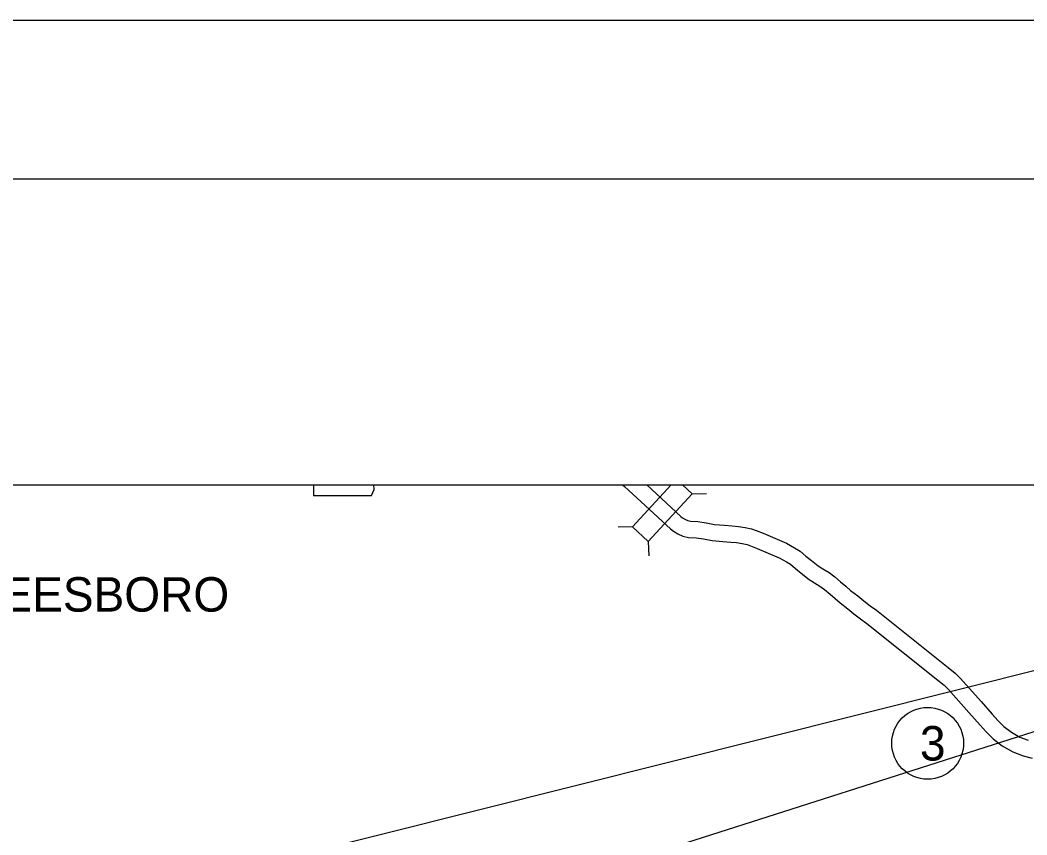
# Model space of a CAD drawing. Extents: x 79818 to 83933, y 50884 to 53307.
# Drawn here: x 81014.4 to 81261.3, y 53107.7 to 53307.5 of the extents above; entities that cross this region are included whole.
import ezdxf

# ---------------------------------------------------------------- set-up
doc = ezdxf.new("R2010")
doc.units = 0
for name, color, linetype in [('Default', 7, 'Continuous'), ('Level 10', 7, 'Continuous'), ('Level 20', 7, 'Continuous'), ('Level 21', 7, 'Continuous'), ('Level 27', 7, 'Continuous'), ('Level 6', 7, 'Continuous'), ('R_Border', 7, 'Continuous'), ('R_No Plot', 7, 'Continuous')]:
    doc.layers.add(name, color=color, linetype=linetype)

msp = doc.modelspace()

# ---------------------------------------------------------------- linework, layer by layer
at = {"layer": 'Default'}
for p in [(81049.64, 53094.55), (81071.88, 53072.06)]:
    msp.add_line(p, (81483.45, 53203.33), dxfattribs=at)
at = {"layer": 'Level 10'}
for points in [[(81162.17, 53193.52), (81162.63, 53193.15), (81173.89, 53182.71), (81174.63, 53182.17), (81175.67, 53181.5), (81176.97, 53180.93), (81178.35, 53180.65), (81180.2, 53180.57), (81181.99, 53180.3), (81184.11, 53179.88), (81186.77, 53179.66), (81188.7, 53179.49), (81190.1, 53179.37), (81191.45, 53179.16), (81192.73, 53178.87), (81193.52, 53178.61), (81195.14, 53177.95), (81200.56, 53175.67), (81202.33, 53174.67), (81203.35, 53174.05), (81204.54, 53173), (81205.96, 53171.85), (81207.88, 53170.34), (81209.21, 53169.54), (81210.54, 53168.73), (81211.68, 53167.88), (81213.03, 53166.72), (81214.28, 53165.69), (81215.48, 53164.58), (81217.4, 53163.14), (81218.86, 53161.94), (81220.48, 53160.66), (81222.04, 53159.56), (81239.5, 53145.64), (81241.06, 53144.42), (81242.09, 53143.33), (81247.11, 53137.72), (81249.83, 53134.62), (81251.29, 53133.01), (81253.05, 53131.28), (81255.28, 53129.57), (81257.84, 53128.1), (81260.42, 53127.09), (81262.63, 53126.51)], [(81168.11, 53193.52), (81176.45, 53185.79), (81176.89, 53185.46), (81177.56, 53185.04), (81178.19, 53184.76), (81178.84, 53184.63), (81180.59, 53184.56), (81182.68, 53184.24), (81184.67, 53183.85), (81187.11, 53183.64), (81189.05, 53183.48), (81190.59, 53183.35), (81192.2, 53183.09), (81193.81, 53182.73), (81194.91, 53182.36), (81196.67, 53181.65), (81202.32, 53179.27), (81204.35, 53178.13), (81205.74, 53177.29), (81207.12, 53176.05), (81208.46, 53174.97), (81210.16, 53173.64), (81211.29, 53172.96), (81212.78, 53172.04), (81214.18, 53171.01), (81215.61, 53169.78), (81216.91, 53168.7), (81218.04, 53167.66), (81219.87, 53166.29), (81221.36, 53165.06), (81222.87, 53163.87), (81224.44, 53162.77), (81241.98, 53148.77), (81243.75, 53147.39), (81245.03, 53146.05), (81250.1, 53140.38), (81252.82, 53137.28), (81254.18, 53135.78), (81255.67, 53134.31), (81257.51, 53132.91), (81259.58, 53131.71), (81261.66, 53130.9)]]:
    msp.add_lwpolyline(points, dxfattribs=at)
at = {"layer": 'Level 20'}
for p, q in [((81179.22, 53191.3), (81182.73, 53191.43)), ((81164.58, 53183.27), (81161.06, 53183.14)), ((81168.45, 53179.68), (81168.58, 53176.16))]:
    msp.add_line(p, q, dxfattribs=at)
msp.add_lwpolyline([(81174.08, 53193.52), (81164.58, 53183.27), (81168.45, 53179.68), (81179.22, 53191.3), (81176.82, 53193.52)], dxfattribs=at)
at = {"layer": 'Level 21'}
msp.add_lwpolyline([(81086.37, 53193.52), (81086.37, 53190.91), (81100.58, 53190.91), (81101.26, 53192.38), (81101.15, 53193.52)], dxfattribs=at)
at = {"layer": 'Level 27'}
msp.add_circle((81236.97, 53130.17), 8.8, dxfattribs=at)
at = {"layer": 'R_Border'}
msp.add_line((80723.6, 53268.52), (83885.4, 53268.52), dxfattribs=at)
at = {"layer": 'R_No Plot'}
msp.add_line((80599.59, 53307.47), (83932.93, 53307.47), dxfattribs=at)
for points in [[(80599.53, 53307.47), (83932.93, 53307.47), (83932.93, 51174.09), (80599.53, 51174.09)], [(80798.6, 53193.52), (81459.98, 53193.52), (81459.98, 52610.7), (80798.6, 52610.7)], [(80798.6, 53193.52), (81459.98, 53193.52), (81459.98, 52610.7), (80798.6, 52610.7)]]:
    msp.add_lwpolyline(points, close=True, dxfattribs=at)

# ---------------------------------------------------------------- texts
at = {"layer": 'Level 27'}
msp.add_text('3', height=8.45, dxfattribs=at).set_placement((81235.08, 53125.95))
at = {"layer": 'Level 6'}
msp.add_text('MURFREESBORO', height=8.448, dxfattribs=at).set_placement((80969.02, 53162.45))

doc.saveas('drawing.dxf')
